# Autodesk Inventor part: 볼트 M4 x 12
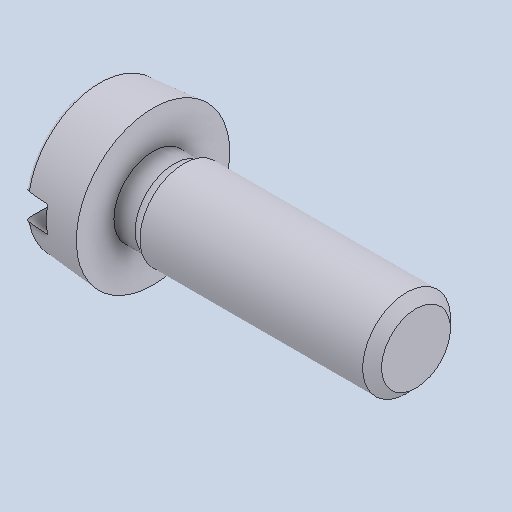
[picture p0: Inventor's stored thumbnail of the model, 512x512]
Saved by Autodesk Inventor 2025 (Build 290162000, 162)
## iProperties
Created: 2024-07
Part Number: 볼트 M4 x 12
Material: 강철, 연강
Description: 6각머리 태핑 나사
Document SubType Name: Modeling
Designer: parkm
Density: 7.85 g/cm^3
Appearance: 기본값
Author: jhkim
Sending System: Autodesk Inventor 2025
Preprocessor: ST-DEVELOPER v20
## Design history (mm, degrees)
feature "Solid1"
node "솔리드1"
